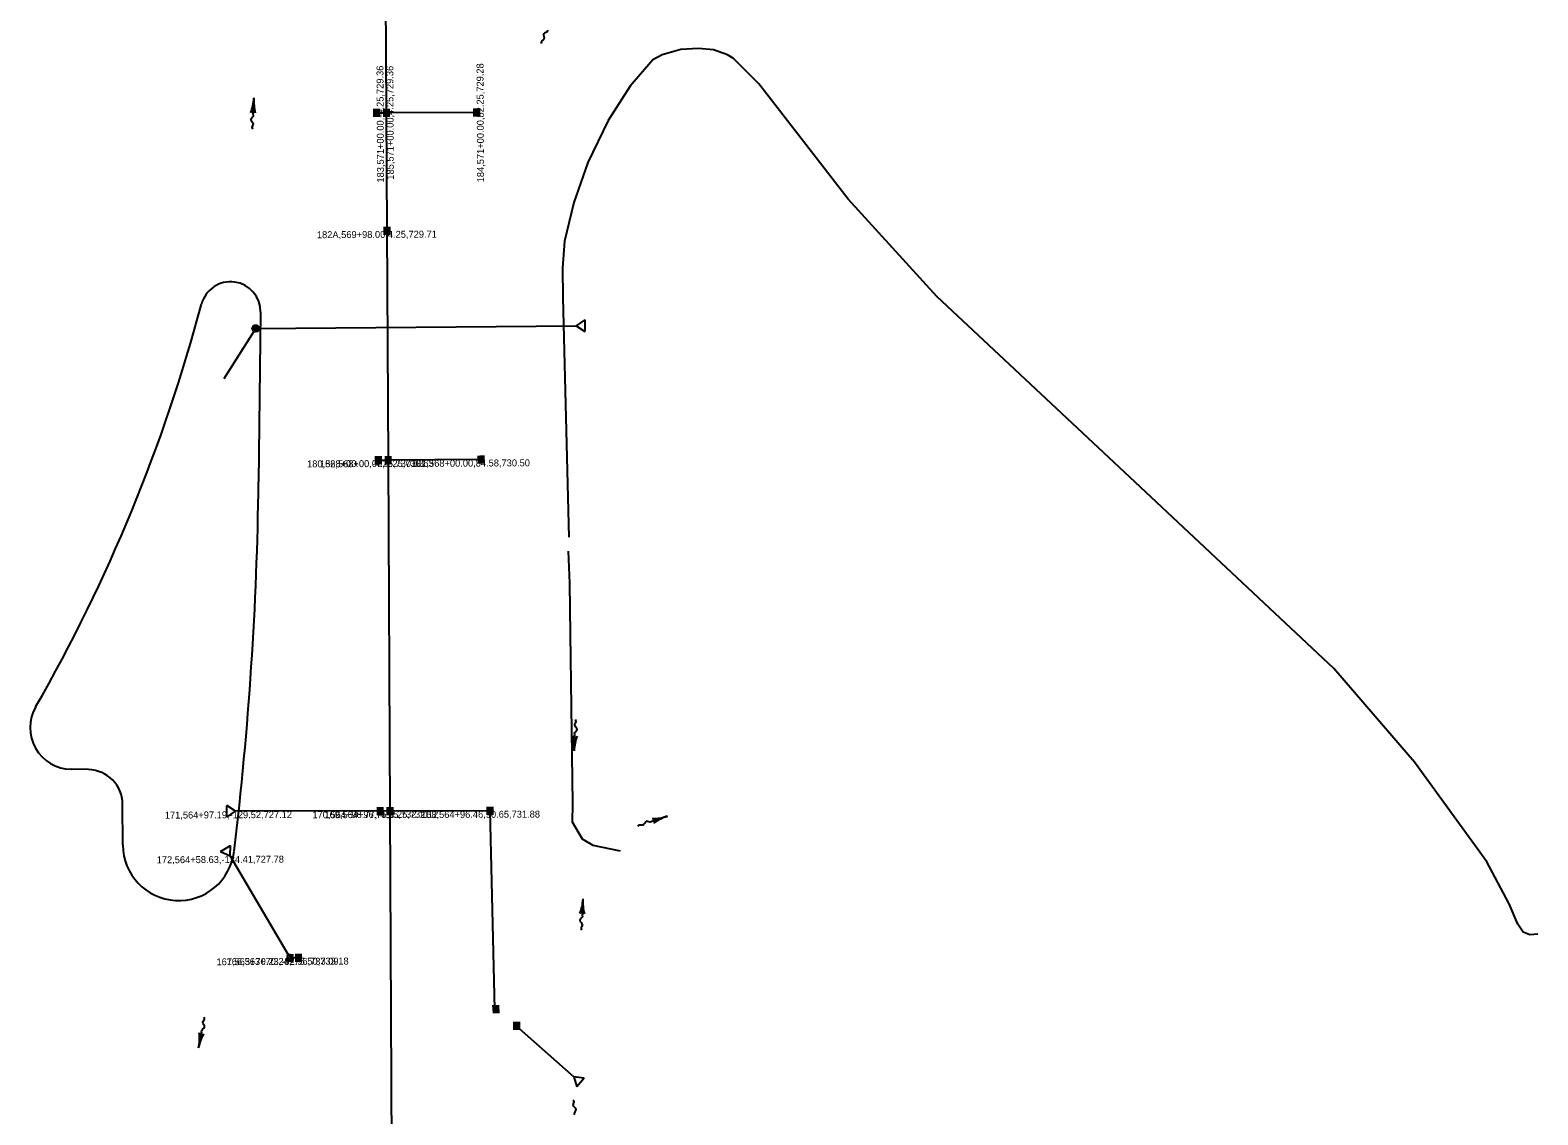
# Model space of a CAD drawing. Extents: x 593481 to 595859, y 150220 to 157407.
# Drawn here: x 594042 to 595346, y 155509 to 156447 of the extents above; entities that cross this region are included whole.
import ezdxf

# ---------------------------------------------------------------- set-up
doc = ezdxf.new("R2010")
doc.units = 0
for name, color, linetype in [('E_PROF_GridMin', 7, 'Continuous'), ('P_ALI_200_Equation', 7, 'Continuous'), ('P_ALI_20_Tic', 7, 'Continuous'), ('P_ALI_50_Equation', 7, 'Continuous'), ('P_DRN_Pond', 7, 'Continuous'), ('P_DRN_SS_UG', 7, 'Continuous'), ('P_RDWY_C_and_G_H', 7, 'Continuous')]:
    doc.layers.add(name, color=color, linetype=linetype)

msp = doc.modelspace()

# ---------------------------------------------------------------- linework, layer by layer
at = {"layer": 'E_PROF_GridMin'}
for p, q in [((594350.5, 156375.2), (594349, 156675.2)), ((594342, 156375.2), (594350.5, 156375.2)), ((594428.5, 156375.6), (594350.5, 156375.2)), ((594352.1, 156075.2), (594350.5, 156375.2)), ((594210.2, 156145.7), (594237.4, 156188.9)), ((594237.4, 156188.9), (594514.4, 156191.3)), ((594343.6, 156075.2), (594352.1, 156075.2)), ((594432.4, 156075.6), (594352.1, 156075.2)), ((594353.6, 155772), (594352.1, 156075.2)), ((594440, 155772.1), (594219.8, 155771.7)), ((594355.1, 155475.2), (594353.6, 155772)), ((594444.2, 155600.7), (594440, 155772.1)), ((594267.1, 155645), (594215.2, 155733.2)), ((594274.5, 155645.1), (594267, 155645)), ((594462.4, 155586.4), (594512.3, 155542.2))]:
    msp.add_line(p, q, dxfattribs=at)
for points in [[(595345.8, 155665.5), (595338.9, 155664.9), (595333.1, 155667.3), (595328.4, 155674.3), (595321, 155691.9), (595301.8, 155728.2), (595239.2, 155814.2), (595169.4, 155895), (594997.8, 156056.2), (594907.2, 156140.8), (594826.3, 156216.4), (594749.6, 156300.6), (594672.2, 156400.2), (594650.5, 156422.2), (594645.2, 156425.4), (594633, 156429.8), (594620.3, 156430.9), (594605, 156429.9), (594588.7, 156425.4), (594580.7, 156420.9), (594561, 156398.2), (594542.2, 156368.7), (594524.6, 156332.4), (594512.5, 156297.9), (594504.2, 156264.4), (594502.7, 156240.9), (594503, 156215.3), (594508, 156008.7)], [(594552.8, 155737.4), (594529.2, 155742.3), (594520, 155747.6), (594511.1, 155762.2), (594511.5, 155778.5), (594509.6, 155924.8), (594508.9, 155968.8), (594507.7, 155996.4)]]:
    msp.add_lwpolyline(points, dxfattribs=at)
at = {"layer": 'P_ALI_200_Equation'}
for radius in [2.98, 2.4, 1.8, 1.2, 0.6]:
    msp.add_circle((594237.4, 156188.9), radius, dxfattribs=at)
at = {"layer": 'P_ALI_20_Tic'}
for p, q in [((594235.8, 156388.1), (594235, 156373.9)), ((594512.6, 155824), (594513.4, 155838.1)), ((594593.2, 155767.5), (594579.8, 155763)), ((594520.3, 155696), (594519.5, 155681.9)), ((594188, 155567.3), (594190.7, 155581.2))]:
    msp.add_line(p, q, dxfattribs=at)
for points in [[(594237.1, 156375.2), (594235.3, 156378.5), (594233.1, 156375.4)], [(594511.3, 155836.9), (594513.1, 155833.6), (594515.3, 155836.7)], [(594581.7, 155761.6), (594584.1, 155764.5), (594580.5, 155765.4)], [(594521.6, 155683.1), (594519.8, 155686.4), (594517.6, 155683.3)], [(594188.5, 155580.3), (594189.8, 155576.7), (594192.4, 155579.5)]]:
    msp.add_lwpolyline(points, dxfattribs=at)
for centre, start, end in [((594193.9, 156390.4), 339.0322, 356.7946), ((594277.7, 156385.7), 176.7946, 194.5569), ((594470.7, 155826.4), 356.7946, 14.5569), ((594554.5, 155821.7), 159.0322, 176.7946), ((594579.9, 155807.3), 270.74, 288.5023), ((594606.6, 155727.7), 108.5023, 126.2646), ((594478.4, 155698.3), 339.0322, 356.7946), ((594562.2, 155693.7), 176.7946, 194.5569), ((594146.8, 155575.3), 349.0067, 6.769), ((594229.2, 155559.3), 151.2443, 169.0067)]:
    msp.add_arc(centre, 42, start, end, dxfattribs=at)
for points in [[(594489.7, 156446.7), (594489.7, 156445.8), (594486.3, 156443.5), (594486.5, 156439), (594484.4, 156436.9), (594484.2, 156435.1)], [(594235, 156373.9), (594235.3, 156373.1), (594233.2, 156369.6), (594235.2, 156365.6), (594234.1, 156362.8), (594234.6, 156361.1)], [(594513.4, 155838.1), (594513.1, 155838.9), (594515.2, 155842.4), (594513.2, 155846.5), (594514.3, 155849.2), (594513.8, 155851)], [(594579.8, 155763), (594579.2, 155762.5), (594575.2, 155763.1), (594572.2, 155759.8), (594569.2, 155759.8), (594567.7, 155758.7)], [(594519.5, 155681.9), (594519.8, 155681.1), (594517.7, 155677.6), (594519.7, 155673.6), (594518.6, 155670.8), (594519.1, 155669)], [(594190.7, 155581.2), (594190.6, 155582), (594193.1, 155585.2), (594191.7, 155589.5), (594193.1, 155592.1), (594192.9, 155593.9)], [(594513.3, 155509.5), (594512.9, 155510.2), (594514.5, 155514), (594511.9, 155517.7), (594512.6, 155520.6), (594511.8, 155522.2)]]:
    msp.add_spline(points, degree=3, dxfattribs=at)
at = {"layer": 'P_DRN_Pond'}
for p, q in [((594241.6, 156203), (594239.8, 156056.5)), ((594092.9, 155807.7), (594077.7, 155808)), ((594122.5, 155742.7), (594122.3, 155777.9))]:
    msp.add_line(p, q, dxfattribs=at)
for centre, radius, start, end in [((594215.6, 156203.3), 26, 359.2941, 165.091), ((592792.2, 156582.3), 1447, 330.142, 345.091), ((591269.1, 156093.1), 2971, 353.1195, 359.2941), ((594078.4, 155844), 36, 150.142, 268.9825), ((594092.3, 155777.7), 30, 0.2941, 88.9825), ((594170.8, 155742.9), 48.3, 180.2941, 353.1195)]:
    msp.add_arc(centre, radius, start, end, dxfattribs=at)
at = {"layer": 'P_DRN_SS_UG'}
for p, q in [((594339.8, 156371.7), (594339.8, 156378.6)), ((594340.7, 156371.7), (594340.7, 156378.6)), ((594341.6, 156371.7), (594341.6, 156378.6)), ((594342.5, 156371.8), (594342.5, 156378.6)), ((594343.4, 156371.8), (594343.4, 156378.6)), ((594344.3, 156371.8), (594344.3, 156378.6)), ((594348.3, 156371.8), (594348.3, 156378.7)), ((594349.2, 156371.8), (594349.2, 156378.7)), ((594350.1, 156371.8), (594350.1, 156378.7)), ((594351, 156371.8), (594351, 156378.7)), ((594351.9, 156371.8), (594351.9, 156378.7)), ((594352.8, 156371.8), (594352.8, 156378.7)), ((594426.3, 156372.2), (594426.3, 156379.1)), ((594427.2, 156372.2), (594427.2, 156379.1)), ((594428.1, 156372.2), (594428.1, 156379.1)), ((594429, 156372.2), (594429, 156379.1)), ((594429.9, 156372.2), (594429.9, 156379.1)), ((594430.8, 156372.2), (594430.8, 156379.1)), ((594348.8, 156269.8), (594348.8, 156276.7)), ((594349.7, 156269.8), (594349.7, 156276.7)), ((594350.6, 156269.8), (594350.6, 156276.7)), ((594351.5, 156269.8), (594351.5, 156276.7)), ((594352.4, 156269.8), (594352.4, 156276.7)), ((594353.3, 156269.8), (594353.3, 156276.7)), ((594341.3, 156071.7), (594341.3, 156078.6)), ((594342.2, 156071.7), (594342.2, 156078.6)), ((594343.1, 156071.8), (594343.1, 156078.6)), ((594344, 156071.8), (594344, 156078.6)), ((594344.9, 156071.8), (594344.9, 156078.6)), ((594345.8, 156071.8), (594345.8, 156078.6)), ((594349.8, 156071.8), (594349.8, 156078.7)), ((594350.7, 156071.8), (594350.7, 156078.7)), ((594351.6, 156071.8), (594351.6, 156078.7)), ((594352.5, 156071.8), (594352.5, 156078.7)), ((594353.4, 156071.8), (594353.4, 156078.7)), ((594354.3, 156071.8), (594354.3, 156078.7)), ((594430.2, 156072.2), (594430.1, 156079)), ((594431.1, 156072.2), (594431, 156079)), ((594432, 156072.2), (594431.9, 156079.1)), ((594432.9, 156072.2), (594432.8, 156079.1)), ((594433.8, 156072.2), (594433.7, 156079.1)), ((594434.7, 156072.3), (594434.6, 156079.1)), ((594342.9, 155768.5), (594342.9, 155775.4)), ((594343.8, 155768.5), (594343.8, 155775.4)), ((594344.7, 155768.5), (594344.7, 155775.4)), ((594345.6, 155768.5), (594345.6, 155775.4)), ((594346.5, 155768.5), (594346.5, 155775.4)), ((594347.4, 155768.5), (594347.4, 155775.4)), ((594351.4, 155768.5), (594351.4, 155775.4)), ((594352.3, 155768.5), (594352.3, 155775.4)), ((594353.2, 155768.5), (594353.2, 155775.4)), ((594354.1, 155768.5), (594354.1, 155775.4)), ((594355, 155768.6), (594355, 155775.4)), ((594355.9, 155768.6), (594355.9, 155775.4)), ((594437.8, 155768.7), (594437.8, 155775.6)), ((594438.7, 155768.7), (594438.7, 155775.6)), ((594439.6, 155768.7), (594439.6, 155775.6)), ((594440.5, 155768.7), (594440.5, 155775.6)), ((594441.4, 155768.7), (594441.4, 155775.6)), ((594442.3, 155768.7), (594442.3, 155775.6)), ((594264.5, 155641.8), (594265.2, 155648.7)), ((594265.4, 155641.7), (594266.1, 155648.6)), ((594266.3, 155641.7), (594267, 155648.5)), ((594267.1, 155641.6), (594267.9, 155648.4)), ((594268, 155641.5), (594268.8, 155648.3)), ((594268.9, 155641.4), (594269.6, 155648.2)), ((594272.3, 155641.6), (594272.3, 155648.5)), ((594273.2, 155641.6), (594273.2, 155648.5)), ((594274.1, 155641.6), (594274.1, 155648.5)), ((594275, 155641.6), (594275, 155648.5)), ((594275.9, 155641.6), (594275.9, 155648.5)), ((594276.8, 155641.6), (594276.8, 155648.5)), ((594443.1, 155597.2), (594442.7, 155604.1)), ((594444, 155597.2), (594443.6, 155604.1)), ((594444.9, 155597.3), (594444.5, 155604.2)), ((594445.8, 155597.3), (594445.4, 155604.2)), ((594446.7, 155597.4), (594446.3, 155604.3)), ((594447.6, 155597.4), (594447.2, 155604.3)), ((594460.6, 155589.8), (594460.6, 155582.9)), ((594461.5, 155589.8), (594461.5, 155582.9)), ((594462.4, 155589.8), (594462.4, 155582.9)), ((594463.3, 155589.8), (594463.3, 155582.9)), ((594464.2, 155589.8), (594464.2, 155582.9)), ((594465.1, 155589.8), (594465.1, 155582.9)), ((594460.5, 155586.2), (594463.5, 155586.2))]:
    msp.add_line(p, q, dxfattribs=at)
for points in [[(594343, 156374.2), (594343, 156376.2), (594341, 156376.2), (594341, 156374.2)], [(594351.5, 156374.2), (594351.5, 156376.2), (594349.5, 156376.2), (594349.5, 156374.2)], [(594429.5, 156374.6), (594429.5, 156376.6), (594427.5, 156376.6), (594427.5, 156374.6)], [(594352.1, 156272.2), (594352, 156274.2), (594350, 156274.2), (594350.1, 156272.2)], [(594344.6, 156074.2), (594344.6, 156076.2), (594342.6, 156076.2), (594342.6, 156074.2)], [(594353.1, 156074.2), (594353.1, 156076.2), (594351.1, 156076.2), (594351.1, 156074.2)], [(594433.4, 156074.7), (594433.4, 156076.7), (594431.4, 156076.6), (594431.4, 156074.6)], [(594346.1, 155771), (594346.1, 155773), (594344.1, 155773), (594344.1, 155771)], [(594354.6, 155771), (594354.6, 155773), (594352.6, 155773), (594352.6, 155771)], [(594441, 155771.1), (594441, 155773.1), (594439, 155773.1), (594439, 155771.1)], [(594267.9, 155643.9), (594268.2, 155645.9), (594266.2, 155646.1), (594266, 155644.1)], [(594275.5, 155644.1), (594275.5, 155646.1), (594273.5, 155646.1), (594273.5, 155644.1)], [(594446.2, 155599.8), (594446.1, 155601.8), (594444.1, 155601.7), (594444.2, 155599.7)]]:
    msp.add_lwpolyline(points, close=True, dxfattribs=at)
at = {"layer": 'P_RDWY_C_and_G_H'}
for p, q in [((594521.9, 156196.4), (594514.4, 156191.3)), ((594514.4, 156191.3), (594521.9, 156186.4)), ((594521.9, 156196.4), (594521.9, 156186.4)), ((594219.8, 155771.7), (594212.3, 155776.7)), ((594212.4, 155766.7), (594212.3, 155776.7)), ((594212.4, 155766.7), (594219.8, 155771.7)), ((594207, 155737.1), (594215.7, 155742.2)), ((594207, 155737.1), (594215.2, 155733.2)), ((594215.2, 155733.2), (594215.7, 155742.2)), ((594521.3, 155541.2), (594512.3, 155542.2)), ((594512.3, 155542.2), (594514.9, 155533.5)), ((594521.3, 155541.2), (594514.9, 155533.5))]:
    msp.add_line(p, q, dxfattribs=at)

# ---------------------------------------------------------------- texts
at = {"layer": 'P_ALI_50_Equation'}
for s, rotation, p in [('183,571+00.00,-4.25,729.36', 90.2941, (594348.3, 156315)), ('185,571+00.00,4.25,729.36', 90.2941, (594356.8, 156317.5)), ('184,571+00.00,82.25,729.28', 90.2941, (594434.8, 156315.2)), ('182A,569+98.00,4.25,729.71', 0.2941, (594290.3, 156266.9)), ('180,568+00.00,-4.25,730.63', 0.2941, (594281.8, 156068.9)), ('182,568+00.00,4.25,730.63', 0.2941, (594292.9, 156068.9)), ('181,568+00.00,84.58,730.50', 0.2941, (594371.6, 156069.3)), ('171,564+97.19,-129.52,727.12', 0.2941, (594158.8, 155765.4)), ('170,564+96.77,-4.25,732.11', 0.2941, (594286.4, 155765.7)), ('169,564+96.75,4.25,732.12', 0.2941, (594296.8, 155765.7)), ('168,564+96.46,90.65,731.88', 0.2941, (594380.3, 155765.8)), ('172,564+58.63,-134.41,727.78', 0.2941, (594151.8, 155726.8)), ('167,563+70.23,-82.96,733.09', 0.2941, (594203.5, 155638.7)), ('166,563+70.24,-75.50,733.18', 0.2941, (594212.2, 155638.8))]:
    msp.add_text(s, height=6, rotation=rotation, dxfattribs=at).set_placement(p)

doc.saveas('drawing.dxf')
